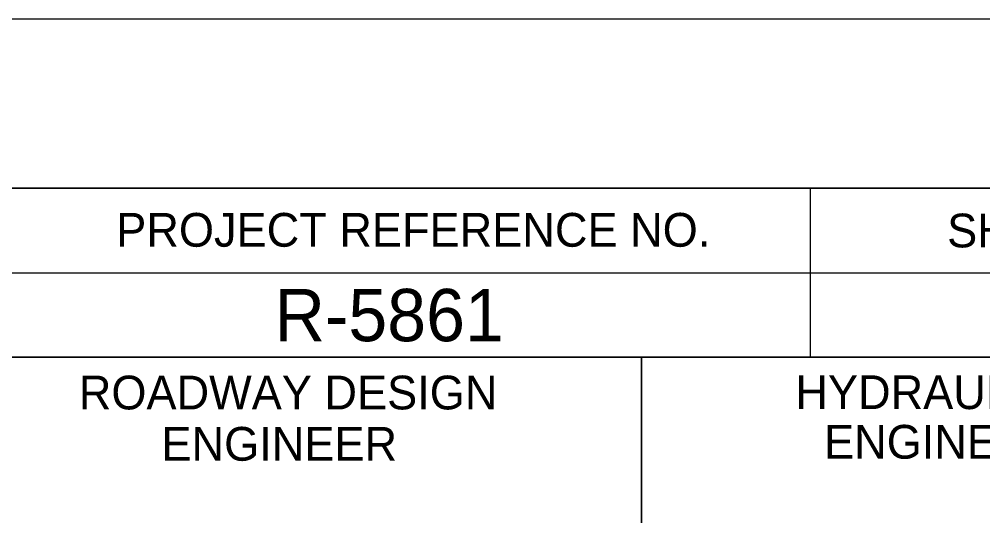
# Model space of a CAD drawing. Extents: x 505602 to 507548, y 483109 to 484209.
# Drawn here: x 507076.9 to 507219.7, y 484135.2 to 484208.7 of the extents above; entities that cross this region are included whole.
import ezdxf

# ---------------------------------------------------------------- set-up
doc = ezdxf.new("R2010")
doc.units = 0
for name, color, linetype in [('Sheet Data Field CELL', 7, 'Continuous'), ('Sheet Plot Border Outside CELL', 7, 'Continuous'), ('Sheet Profile CELL', 7, 'Continuous'), ('Sheet Profile Grid Major CELL', 7, 'Continuous')]:
    doc.layers.add(name, color=color, linetype=linetype)

msp = doc.modelspace()

# ---------------------------------------------------------------- linework, layer by layer
at = {"layer": 'Sheet Plot Border Outside CELL'}
msp.add_lwpolyline([(505602.08, 483108.71), (507286.08, 483108.71), (507286.08, 484208.71), (505602.08, 484208.71)], close=True, dxfattribs=at)
at = {"layer": 'Sheet Profile CELL'}
for p, q in [((507194.08, 484183.66), (507194.08, 484158.66)), ((507069.03, 484171.16), (507269.08, 484171.16)), ((507169.08, 484158.66), (507169.08, 484046.21))]:
    msp.add_line(p, q, dxfattribs=at)
for points in [[(507269.08, 484183.71), (505769.08, 484183.71), (505769.08, 483133.71), (507269.08, 483133.71)], [(507069.03, 484183.71), (507269.08, 484183.71), (507269.08, 484158.66), (507069.03, 484158.66)], [(507069.03, 484158.66), (507169.08, 484158.66), (507169.08, 484046.16), (507069.03, 484046.16)], [(507169.08, 484158.66), (507269.08, 484158.66), (507269.08, 484046.16), (507169.08, 484046.16)]]:
    msp.add_lwpolyline(points, close=True, dxfattribs=at)
at = {"layer": 'Sheet Profile Grid Major CELL'}
msp.add_lwpolyline([(506519.08, 483683.71), (506569.08, 483683.71), (506569.08, 484183.71), (506619.08, 484183.71), (506619.08, 483683.71), (506669.08, 483683.71), (506669.08, 484183.71), (506719.08, 484183.71), (506719.08, 483683.71), (506769.08, 483683.71), (506769.08, 484183.71), (506819.08, 484183.71), (506819.08, 483683.71), (506869.08, 483683.71), (506869.08, 484183.71), (506919.08, 484183.71), (506919.08, 483683.71), (506969.08, 483683.71), (506969.08, 484183.71), (507019.08, 484183.71), (507019.08, 483683.71), (507069.08, 483683.71), (507069.08, 484183.71), (507095.38, 484183.71)], dxfattribs=at)

# ---------------------------------------------------------------- texts
at = {"layer": 'Sheet Data Field CELL'}
msp.add_text('R-5861', height=7.75, dxfattribs=at).set_placement((507114.7, 484161.02))
at = {"layer": 'Sheet Profile CELL'}
for s, height, p in [('PROJECT REFERENCE NO.', 5.0001, (507091.24, 484175.02)), ('SHEET NO.', 5, (507214.39, 484174.92)), ('ROADWAY DESIGN', 5.0001, (507085.69, 484150.92)), ('HYDRAULICS', 5, (507191.89, 484150.97)), ('ENGINEER', 5, (507097.94, 484143.32)), ('ENGINEER', 5, (507196.14, 484143.62))]:
    msp.add_text(s, height=height, dxfattribs=at).set_placement(p)

doc.saveas('drawing.dxf')
